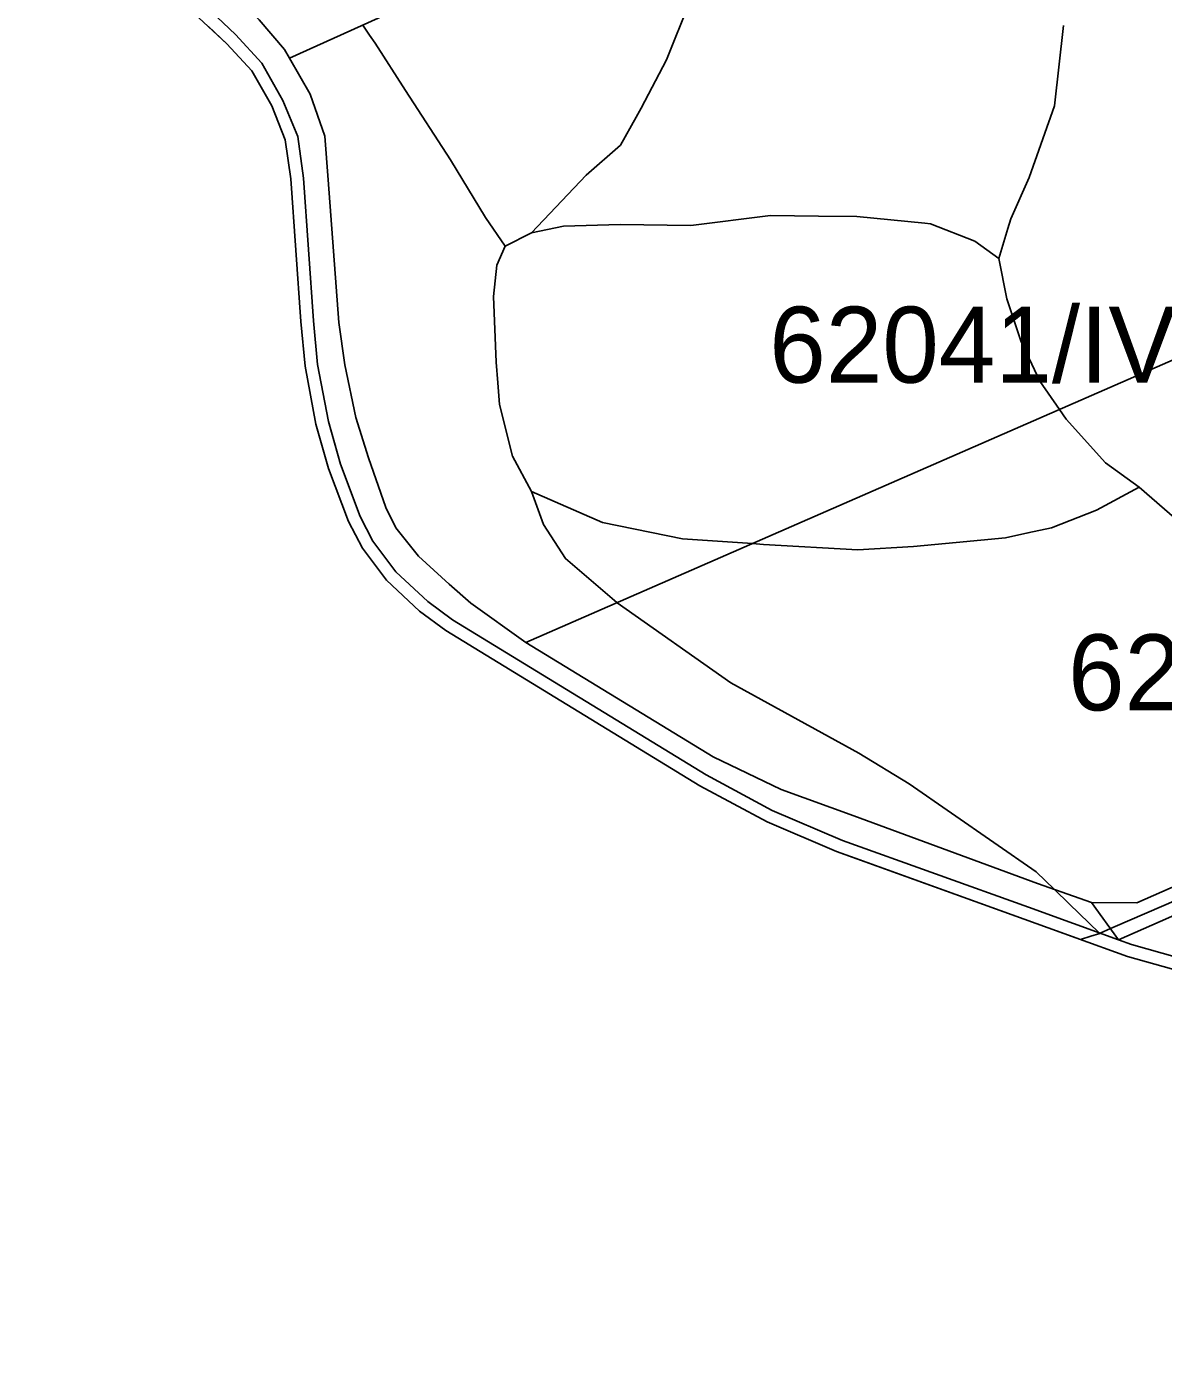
# Model space of a CAD drawing. Extents: x -522079 to -518792, y -1142400 to -1139961.
# Drawn here: x -521476.9 to -521252.6, y -1141773.6 to -1141508 of the extents above; entities that cross this region are included whole.
import ezdxf

# ---------------------------------------------------------------- set-up
doc = ezdxf.new("R2010")
doc.units = 0
for name, color, linetype in [('Hranice parcel', 7, 'Continuous'), ('Parcelní čísla', 7, 'Continuous'), ('Vnitřní kresba', 7, 'Continuous'), ('Značky bodu BP', 7, 'Continuous'), ('Značky budov', 7, 'Continuous')]:
    doc.layers.add(name, color=color, linetype=linetype)

msp = doc.modelspace()

# ---------------------------------------------------------------- linework, layer by layer
at = {"layer": 'Hranice parcel'}
msp.add_lwpolyline([(-521431.09, -1141506.63), (-521426.04, -1141512.48), (-521425.07, -1141514.17), (-521421, -1141521.26), (-521418.07, -1141529.55), (-521417.47, -1141538.2), (-521415.34, -1141566.3), (-521414.13, -1141574.69), (-521412.01, -1141585.06), (-521409.49, -1141593.05), (-521406.05, -1141602.85), (-521404.05, -1141606.86), (-521399.61, -1141612.42), (-521393.54, -1141617.98), (-521389.3, -1141621.72), (-521378.39, -1141629.5), (-521341.44, -1141652.02), (-521328.02, -1141658.46), (-521313.67, -1141663.71), (-521277.4, -1141677.06), (-521266.74, -1141680.79), (-521261.42, -1141688.16), (-521279.18, -1141681.72), (-521315.94, -1141668.52), (-521329.77, -1141662.64), (-521342.84, -1141655.56), (-521392.9, -1141624.99), (-521397.79, -1141621.36), (-521404.06, -1141615.52), (-521408.6, -1141609.5), (-521411.13, -1141604.62), (-521415, -1141594.31), (-521417.39, -1141585.84), (-521419.55, -1141574.63), (-521420.36, -1141565.98), (-521422.3, -1141537.87), (-521423.45, -1141529.64), (-521426.4, -1141522.52), (-521430.56, -1141515.15), (-521435.7, -1141509.5), (-521474.82, -1141472.48)], dxfattribs=at)
msp.add_lwpolyline([(-521257.85, -1141680.84), (-521182.3, -1141647.66), (-521180.65, -1141652.62), (-521185.06, -1141654.56), (-521261.42, -1141688.16), (-521266.74, -1141680.79)], close=True, dxfattribs=at)
at = {"layer": 'Parcelní čísla'}
for points in [[(-521431.09, -1141506.63), (-521455.62, -1141481.81), (-521454.54, -1141476.12), (-521272.96, -1141395.84), (-521159.26, -1141346.88), (-521156.76, -1141348.04), (-521153.82, -1141349.39), (-521142.48, -1141389.44), (-521310.56, -1141462.49), (-521425.07, -1141514.17), (-521426.04, -1141512.48)], [(-521378.39, -1141629.5), (-521389.3, -1141621.72), (-521393.54, -1141617.98), (-521399.61, -1141612.42), (-521404.05, -1141606.86), (-521406.05, -1141602.85), (-521409.49, -1141593.05), (-521412.01, -1141585.06), (-521414.13, -1141574.69), (-521415.34, -1141566.3), (-521417.47, -1141538.2), (-521418.07, -1141529.55), (-521421, -1141521.26), (-521425.07, -1141514.17), (-521310.56, -1141462.49), (-521142.48, -1141389.44), (-521107.96, -1141511.35), (-521234.07, -1141566.44)], [(-521257.85, -1141680.84), (-521266.74, -1141680.79), (-521277.4, -1141677.06), (-521313.67, -1141663.71), (-521328.02, -1141658.46), (-521341.44, -1141652.02), (-521378.39, -1141629.5), (-521234.07, -1141566.44), (-521107.96, -1141511.35), (-521083.41, -1141598.05), (-521086.66, -1141604.9), (-521135.66, -1141627.18), (-521182.3, -1141647.66)]]:
    msp.add_lwpolyline(points, close=True, dxfattribs=at)
at = {"layer": 'Vnitřní kresba'}
for points in [[(-521474.82, -1141472.48), (-521435.7, -1141509.5), (-521430.56, -1141515.15), (-521426.4, -1141522.52), (-521423.45, -1141529.64), (-521422.3, -1141537.87), (-521420.36, -1141565.98), (-521419.55, -1141574.63), (-521417.39, -1141585.84), (-521415, -1141594.31), (-521411.13, -1141604.62), (-521408.6, -1141609.5), (-521404.06, -1141615.52), (-521397.79, -1141621.36), (-521392.9, -1141624.99), (-521342.84, -1141655.56), (-521329.77, -1141662.64), (-521315.94, -1141668.52), (-521279.18, -1141681.72), (-521261.42, -1141688.16), (-521258.87, -1141689.08), (-521246.75, -1141692.49)], [(-521247.24, -1141694.95), (-521259.69, -1141691.44), (-521280.03, -1141684.05), (-521317.08, -1141670.75), (-521330.81, -1141664.89), (-521344.1, -1141657.73), (-521394.19, -1141627.12), (-521399.42, -1141623.32), (-521405.95, -1141617.2), (-521410.67, -1141610.84), (-521413.41, -1141605.57), (-521417.34, -1141595.15), (-521419.85, -1141586.36), (-521421.99, -1141574.92), (-521422.84, -1141566.15), (-521424.81, -1141537.99), (-521425.94, -1141530.31), (-521428.59, -1141523.58), (-521432.52, -1141516.64), (-521437.41, -1141511.31), (-521476.9, -1141474.65)]]:
    msp.add_lwpolyline(points, dxfattribs=at)
at = {"layer": 'Značky bodu BP'}
for points in [[(-521346.12, -1141503.16), (-521350.65, -1141514.51), (-521355.64, -1141524.06), (-521356.63, -1141525.82), (-521359.71, -1141531.33), (-521366.51, -1141537.24), (-521377.32, -1141548.65), (-521382.51, -1141551.25), (-521386.41, -1141545.61), (-521393.27, -1141534.25), (-521402.15, -1141520.52), (-521408.17, -1141511.22), (-521409.25, -1141509.65), (-521410.62, -1141507.65)], [(-521272.28, -1141507.7), (-521274.09, -1141523.6), (-521279.08, -1141537.69), (-521282.7, -1141545.87), (-521283.29, -1141547.81), (-521285.08, -1141553.69), (-521289.78, -1141550.27), (-521298.53, -1141546.86), (-521299.66, -1141546.75), (-521313.12, -1141545.4), (-521320.68, -1141545.32), (-521330.15, -1141545.23), (-521345.87, -1141547.18), (-521359.81, -1141547.02), (-521371, -1141547.35), (-521377.32, -1141548.65), (-521366.51, -1141537.24), (-521359.71, -1141531.33), (-521356.63, -1141525.82), (-521355.64, -1141524.06), (-521350.65, -1141514.51), (-521346.12, -1141503.16)], [(-521410.62, -1141507.65), (-521409.25, -1141509.65), (-521408.17, -1141511.22), (-521402.15, -1141520.52), (-521393.27, -1141534.25), (-521386.41, -1141545.61), (-521382.51, -1141551.25), (-521384.13, -1141554.99), (-521384.78, -1141561.17), (-521384.29, -1141574.18), (-521383.98, -1141578.21), (-521383.65, -1141582.48), (-521381.05, -1141592.72), (-521377.32, -1141599.7), (-521374.94, -1141606.2), (-521370.61, -1141612.93), (-521360.45, -1141621.6), (-521360.4, -1141621.64), (-521337.97, -1141637.43), (-521312.68, -1141651.31), (-521302.74, -1141657.38), (-521277.67, -1141674.73), (-521274.06, -1141678.23), (-521271.16, -1141681.04), (-521265.26, -1141686.76), (-521265.17, -1141686.85), (-521265.13, -1141686.9), (-521266.91, -1141687.44), (-521268.94, -1141688.07), (-521280.03, -1141684.05), (-521313.43, -1141672.06), (-521317.08, -1141670.75), (-521330.81, -1141664.89), (-521344.1, -1141657.73), (-521394.19, -1141627.12), (-521399.42, -1141623.32), (-521405.95, -1141617.2), (-521410.67, -1141610.84), (-521413.41, -1141605.57), (-521417.34, -1141595.15), (-521419.85, -1141586.36), (-521421.99, -1141574.92), (-521422.84, -1141566.15), (-521424.81, -1141537.99), (-521425.94, -1141530.31), (-521428.59, -1141523.58), (-521432.52, -1141516.64), (-521437.41, -1141511.31), (-521441.06, -1141507.92)], [(-521239.84, -1141614.01), (-521257.35, -1141598.83), (-521264, -1141594.02), (-521271.78, -1141585.4), (-521273.1, -1141583.5), (-521276.97, -1141577.92), (-521280.7, -1141569.95), (-521283.46, -1141561.66), (-521285.08, -1141553.69), (-521283.29, -1141547.81), (-521282.7, -1141545.87), (-521279.08, -1141537.69), (-521274.09, -1141523.6), (-521272.28, -1141507.7)], [(-521204.3, -1141660.61), (-521262.08, -1141685.51), (-521263.02, -1141685.94), (-521265.03, -1141686.85), (-521265.13, -1141686.9), (-521265.17, -1141686.85), (-521265.26, -1141686.76), (-521271.16, -1141681.04), (-521274.06, -1141678.23), (-521277.67, -1141674.73), (-521302.74, -1141657.38), (-521312.68, -1141651.31), (-521337.97, -1141637.43), (-521360.4, -1141621.64), (-521360.45, -1141621.6), (-521370.61, -1141612.93), (-521374.94, -1141606.2), (-521377.32, -1141599.7), (-521363.26, -1141605.77), (-521347.49, -1141609.02), (-521333.68, -1141609.96), (-521331.49, -1141610.11), (-521312.9, -1141611.19), (-521301.88, -1141610.54), (-521293.45, -1141609.74), (-521283.72, -1141608.81), (-521279.31, -1141607.86), (-521274.64, -1141606.85), (-521265.78, -1141603.38), (-521257.35, -1141598.83), (-521239.84, -1141614.01)], [(-521247.24, -1141694.95), (-521259.69, -1141691.44), (-521280.03, -1141684.05), (-521268.94, -1141688.07), (-521266.91, -1141687.44), (-521265.13, -1141686.9), (-521265.03, -1141686.85), (-521263.02, -1141685.94), (-521262.08, -1141685.51), (-521204.3, -1141660.61)]]:
    msp.add_lwpolyline(points, dxfattribs=at)
msp.add_lwpolyline([(-521298.53, -1141546.86), (-521289.78, -1141550.27), (-521285.08, -1141553.69), (-521283.46, -1141561.66), (-521280.7, -1141569.95), (-521276.97, -1141577.92), (-521273.1, -1141583.5), (-521271.78, -1141585.4), (-521264, -1141594.02), (-521257.35, -1141598.83), (-521265.78, -1141603.38), (-521274.64, -1141606.85), (-521279.31, -1141607.86), (-521283.72, -1141608.81), (-521293.45, -1141609.74), (-521301.88, -1141610.54), (-521312.9, -1141611.19), (-521331.49, -1141610.11), (-521333.68, -1141609.96), (-521347.49, -1141609.02), (-521363.26, -1141605.77), (-521377.32, -1141599.7), (-521381.05, -1141592.72), (-521383.65, -1141582.48), (-521383.98, -1141578.21), (-521384.29, -1141574.18), (-521384.78, -1141561.17), (-521384.13, -1141554.99), (-521382.51, -1141551.25), (-521377.32, -1141548.65), (-521371, -1141547.35), (-521359.81, -1141547.02), (-521345.87, -1141547.18), (-521330.15, -1141545.23), (-521320.68, -1141545.32), (-521313.12, -1141545.4), (-521299.66, -1141546.75)], close=True, dxfattribs=at)
at = {"layer": 'Značky budov'}
msp.add_lwpolyline([(-521261.42, -1141688.16), (-521185.06, -1141654.56), (-521146.44, -1141773.64), (-521153.73, -1141764.26), (-521160.88, -1141756.78), (-521181.74, -1141737.31), (-521186.22, -1141732.52), (-521191.06, -1141726.58), (-521193.87, -1141721.1), (-521196.27, -1141715.36), (-521198.1, -1141710.58), (-521201.07, -1141705.38), (-521205.36, -1141700.71), (-521210.58, -1141697.9), (-521216.85, -1141696.44), (-521234.23, -1141694.42), (-521246.75, -1141692.49), (-521258.87, -1141689.08)], close=True, dxfattribs=at)

# ---------------------------------------------------------------- texts
at = {"layer": 'Značky bodu BP'}
for s, p in [('62041/IV.', (-521330.37, -1141578.21)), ('62441/III.', (-521271.4, -1141642.87))]:
    msp.add_text(s, height=15, rotation=360, dxfattribs=at).set_placement(p)

doc.saveas('drawing.dxf')
